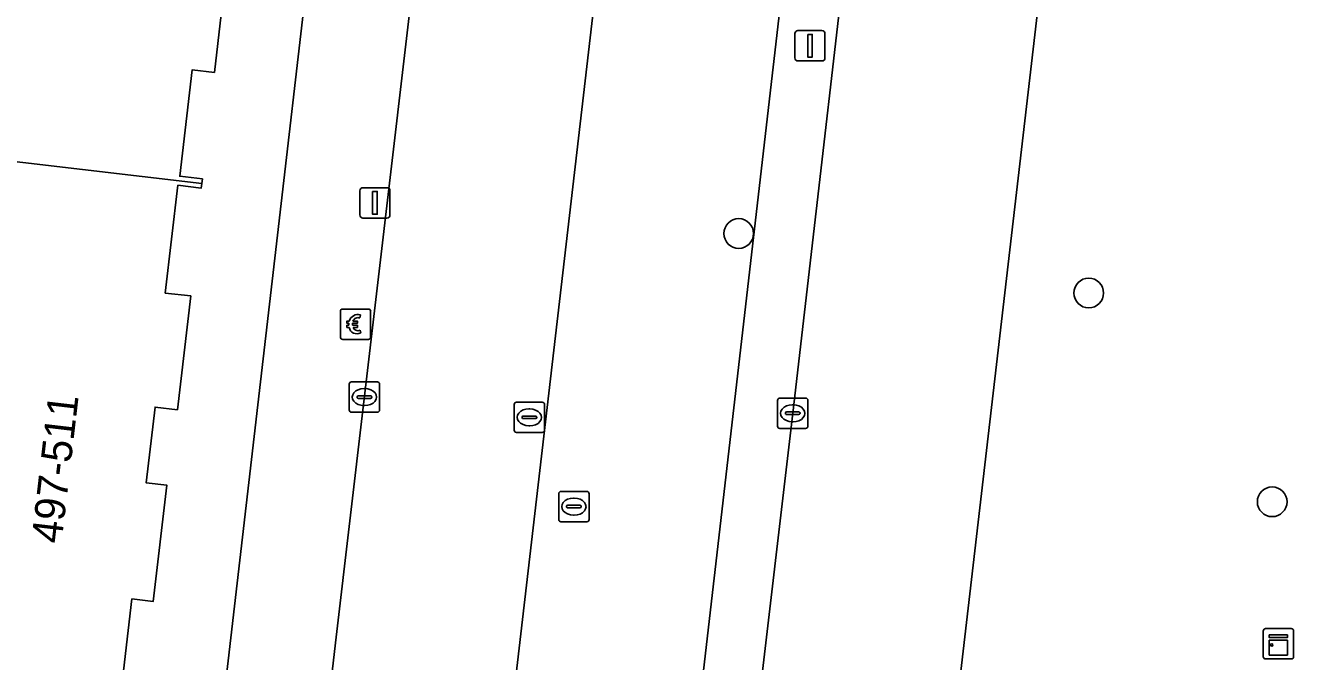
# Model space of a CAD drawing. Extents: x 160856 to 161310, y 384024 to 384878.
# Drawn here: x 161229.52 to 161271.35, y 384514 to 384534.96 of the extents above; entities that cross this region are included whole.
import ezdxf

# ---------------------------------------------------------------- set-up
doc = ezdxf.new("R2010")
doc.units = 0
for name, color, linetype in [('IMGEO_Berm_groen', 7, 'Continuous'), ('IMGEO_Betaalautomaat', 7, 'Continuous'), ('IMGEO_Boom', 7, 'Continuous'), ('IMGEO_Erf', 7, 'Continuous'), ('IMGEO_Kast', 7, 'Continuous'), ('IMGEO_Kolk', 7, 'Continuous'), ('IMGEO_Lichtmast', 7, 'Continuous'), ('IMGEO_Pand', 7, 'Continuous'), ('IMGEO_Pand_nummerreeks', 7, 'Continuous'), ('IMGEO_Parkeervlak_open', 7, 'Continuous'), ('IMGEO_Rijbaan_lokaal_gesloten', 7, 'Continuous'), ('IMGEO_Rijbaan_lokaal_open', 7, 'Continuous'), ('IMGEO_Rioolput', 7, 'Continuous'), ('IMGEO_Voetpad_open', 7, 'Continuous')]:
    doc.layers.add(name, color=color, linetype=linetype)

msp = doc.modelspace()

# ---------------------------------------------------------------- linework, layer by layer
at = {"layer": 'IMGEO_Berm_groen'}
for points in [[(161271.226, 384656.034), (161271.075, 384657.442), (161268.546, 384657.7), (161262.738, 384608.287), (161261.545, 384598.151), (161258.141, 384567.697), (161257.931, 384565.814), (161257.361, 384560.886), (161251.303, 384561.613), (161250.737, 384556.74), (161256.785, 384556.041), (161251.596, 384511.132), (161250.377, 384500), (161238.15, 384396.266), (161238.006, 384395.04), (161236.799, 384395.17)], [(161254.83, 384522.177), (161257.178, 384542.439), (161259.33, 384560.777), (161261.579, 384580.114), (161261.966, 384583.337)], [(161269.166, 384580.645), (161268.148, 384576.401), (161267.446, 384572.759), (161266.816, 384568.826), (161266.33, 384564.879), (161259.354, 384504.899), (161254.88, 384466.32), (161245.611, 384386.656)], [(161237.241, 384373.124), (161237.25, 384373.157), (161237.479, 384374.076), (161237.563, 384374.434), (161237.763, 384375.367), (161238.178, 384378.283), (161238.653, 384382.516), (161239.6, 384390.894), (161241.912, 384411.162), (161243.88, 384428.499), (161246.021, 384446.828), (161247.876, 384462.682), (161250.03, 384480.998), (161252.438, 384501.823), (161254.83, 384522.177)]]:
    msp.add_lwpolyline(points, dxfattribs=at)
at = {"layer": 'IMGEO_Betaalautomaat'}
for p, q in [((161239.911, 384524.688), (161239.911, 384525.529)), ((161239.911, 384525.529), (161239.911, 384524.688)), ((161239.986, 384525.612), (161240.827, 384525.612)), ((161240.827, 384525.612), (161239.986, 384525.612)), ((161240.91, 384525.538), (161240.91, 384524.697)), ((161240.91, 384524.697), (161240.91, 384525.538)), ((161240.194, 384525.076), (161240.194, 384525.144)), ((161240.315, 384525.144), (161240.315, 384525.076)), ((161240.573, 384525.417), (161240.556, 384525.317)), ((161240.56, 384524.911), (161240.582, 384524.824)), ((161240.836, 384524.613), (161239.995, 384524.613)), ((161239.995, 384524.613), (161240.836, 384524.613))]:
    msp.add_line(p, q, dxfattribs=at)
for points in [[(161240.194, 384525.144), (161240.125, 384525.144), (161240.125, 384525.213), (161240.204, 384525.213)], [(161240.199, 384525.007), (161240.125, 384525.007), (161240.125, 384525.076), (161240.194, 384525.076)], [(161240.326, 384525.213), (161240.473, 384525.213), (161240.473, 384525.144), (161240.315, 384525.144)], [(161240.315, 384525.076), (161240.473, 384525.076), (161240.473, 384525.007), (161240.329, 384525.007)]]:
    msp.add_lwpolyline(points, dxfattribs=at)
for centre, radius, start, end in [((161239.989, 384525.535), 0.0779, 92.4484, 184.2845), ((161239.989, 384525.535), 0.0779, 92.4484, 184.2845), ((161240.833, 384525.535), 0.0779, 2.4484, 94.2845), ((161240.833, 384525.535), 0.0779, 2.4484, 94.2845), ((161240.487, 384525.137), 0.293, 73.014, 165.0139), ((161240.493, 384525.15), 0.179, 69.3236, 159.5683), ((161239.989, 384524.691), 0.0779, 182.4484, 274.2845), ((161239.989, 384524.691), 0.0779, 182.4484, 274.2845), ((161240.46, 384525.062), 0.267, 191.8096, 297.0389), ((161240.493, 384525.077), 0.179, 202.7625, 291.8693), ((161240.833, 384524.691), 0.0779, 272.4484, 4.2845), ((161240.833, 384524.691), 0.0779, 272.4484, 4.2845)]:
    msp.add_arc(centre, radius, start, end, dxfattribs=at)
at = {"layer": 'IMGEO_Boom'}
for centre in [(161253.048, 384528.1), (161264.594, 384526.14), (161270.643, 384519.261)]:
    msp.add_circle(centre, 0.489, dxfattribs=at)
at = {"layer": 'IMGEO_Erf'}
for points in [[(161234.582, 384500), (161242.07, 384564.539)], [(161236.204, 384537.232), (161235.756, 384533.408), (161235.024, 384533.494), (161234.613, 384529.988), (161235.359, 384529.901), (161235.341, 384529.749), (161235.324, 384529.598), (161234.553, 384529.688), (161234.137, 384526.139), (161234.975, 384526.042), (161234.536, 384522.296), (161233.803, 384522.382), (161233.511, 384519.883), (161234.189, 384519.804), (161233.741, 384515.981), (161233.034, 384516.064), (161232.635, 384512.65)]]:
    msp.add_lwpolyline(points, dxfattribs=at)
at = {"layer": 'IMGEO_Kast'}
for p, q in [((161270.426, 384515.084), (161271.267, 384515.084)), ((161271.267, 384515.084), (161270.426, 384515.084)), ((161270.351, 384514.159), (161270.351, 384515)), ((161270.351, 384515), (161270.351, 384514.159)), ((161271.351, 384515.009), (161271.351, 384514.168)), ((161271.351, 384514.168), (161271.351, 384515.009)), ((161271.276, 384514.084), (161270.435, 384514.084)), ((161270.435, 384514.084), (161271.276, 384514.084))]:
    msp.add_line(p, q, dxfattribs=at)
for points in [[(161270.546, 384514.874), (161271.146, 384514.874), (161271.146, 384514.789), (161270.546, 384514.789), (161270.546, 384514.874)], [(161270.546, 384514.699), (161271.146, 384514.699), (161271.146, 384514.21), (161270.546, 384514.21), (161270.546, 384514.699)]]:
    msp.add_lwpolyline(points, dxfattribs=at)
msp.add_circle((161270.63, 384514.548), 0.0377, dxfattribs=at)
for centre, start, end in [((161270.429, 384515.006), 92.4484, 184.2845), ((161270.429, 384515.006), 92.4484, 184.2845), ((161271.273, 384515.006), 2.4484, 94.2845), ((161271.273, 384515.006), 2.4484, 94.2845), ((161270.429, 384514.162), 182.4484, 274.2845), ((161270.429, 384514.162), 182.4484, 274.2845), ((161271.273, 384514.162), 272.4484, 4.2845), ((161271.273, 384514.162), 272.4484, 4.2845)]:
    msp.add_arc(centre, 0.0779, start, end, dxfattribs=at)
at = {"layer": 'IMGEO_Kolk'}
for p, q in [((161240.204, 384522.286), (161240.204, 384523.138)), ((161240.279, 384523.212), (161241.131, 384523.212)), ((161240.692, 384522.992), (161240.717, 384522.992)), ((161241.205, 384523.138), (161241.205, 384522.286)), ((161240.463, 384522.706), (161240.463, 384522.718)), ((161240.901, 384522.669), (161240.503, 384522.669)), ((161240.506, 384522.755), (161240.904, 384522.755)), ((161240.947, 384522.718), (161240.947, 384522.706)), ((161254.329, 384521.751), (161254.329, 384522.603)), ((161254.404, 384522.677), (161255.256, 384522.677)), ((161255.33, 384522.603), (161255.33, 384521.751)), ((161241.131, 384522.212), (161240.279, 384522.212)), ((161240.715, 384522.432), (161240.69, 384522.432)), ((161245.644, 384521.618), (161245.644, 384522.47)), ((161245.719, 384522.544), (161246.571, 384522.544)), ((161246.132, 384522.324), (161246.157, 384522.324)), ((161246.645, 384522.47), (161246.645, 384521.618)), ((161254.588, 384522.171), (161254.588, 384522.183)), ((161254.631, 384522.22), (161255.029, 384522.22)), ((161254.817, 384522.457), (161254.842, 384522.457)), ((161255.072, 384522.183), (161255.072, 384522.171)), ((161245.903, 384522.038), (161245.903, 384522.05)), ((161246.341, 384522.001), (161245.943, 384522.001)), ((161245.946, 384522.087), (161246.344, 384522.087)), ((161246.155, 384521.764), (161246.13, 384521.764)), ((161246.387, 384522.05), (161246.387, 384522.038)), ((161255.026, 384522.134), (161254.628, 384522.134)), ((161254.84, 384521.897), (161254.815, 384521.897)), ((161246.571, 384521.544), (161245.719, 384521.544)), ((161255.256, 384521.677), (161254.404, 384521.677))]:
    msp.add_line(p, q, dxfattribs=at)
for points in [[(161240.204, 384522.286), (161240.204, 384523.138)], [(161240.279, 384523.212), (161241.131, 384523.212)], [(161241.205, 384523.138), (161241.205, 384522.286)], [(161254.329, 384521.751), (161254.329, 384522.603)], [(161254.404, 384522.677), (161255.256, 384522.677)], [(161255.33, 384522.603), (161255.33, 384521.751)], [(161241.131, 384522.212), (161240.279, 384522.212)], [(161245.644, 384521.618), (161245.644, 384522.47)], [(161245.719, 384522.544), (161246.571, 384522.544)], [(161246.645, 384522.47), (161246.645, 384521.618)], [(161246.571, 384521.544), (161245.719, 384521.544)], [(161255.256, 384521.677), (161254.404, 384521.677)]]:
    msp.add_lwpolyline(points, dxfattribs=at)
for centre, radius, start, end in [((161240.281, 384523.136), 0.0765, 91.552, 178.448), ((161240.281, 384523.136), 0.0765, 91.552, 178.448), ((161241.129, 384523.136), 0.0765, 1.552, 88.448), ((161241.129, 384523.136), 0.0765, 1.552, 88.448), ((161240.503, 384522.715), 0.0403, 85.8775, 175.7526), ((161240.5, 384522.705), 0.0366, 178.938, 274.7102), ((161240.904, 384522.712), 0.043, 264.8664, 352.4533), ((161240.908, 384522.717), 0.0386, 1.7309, 96.639), ((161254.406, 384522.601), 0.0765, 91.552, 178.448), ((161254.406, 384522.601), 0.0765, 91.552, 178.448), ((161255.254, 384522.601), 0.0765, 1.552, 88.448), ((161255.254, 384522.601), 0.0765, 1.552, 88.448), ((161240.281, 384522.288), 0.0765, 181.552, 268.448), ((161240.281, 384522.288), 0.0765, 181.552, 268.448), ((161241.129, 384522.288), 0.0765, 271.552, 358.448), ((161241.129, 384522.288), 0.0765, 271.552, 358.448), ((161245.721, 384522.468), 0.0765, 91.552, 178.448), ((161245.721, 384522.468), 0.0765, 91.552, 178.448), ((161246.569, 384522.468), 0.0765, 1.552, 88.448), ((161246.569, 384522.468), 0.0765, 1.552, 88.448), ((161254.628, 384522.18), 0.0403, 85.8775, 175.7526), ((161254.625, 384522.17), 0.0366, 178.938, 274.7102), ((161255.029, 384522.177), 0.043, 264.8664, 352.4533), ((161255.033, 384522.182), 0.0386, 1.7309, 96.639), ((161245.943, 384522.047), 0.0403, 85.8775, 175.7526), ((161245.94, 384522.037), 0.0366, 178.938, 274.7102), ((161246.344, 384522.044), 0.043, 264.8664, 352.4533), ((161246.348, 384522.049), 0.0386, 1.7309, 96.639), ((161254.406, 384521.753), 0.0765, 181.552, 268.448), ((161254.406, 384521.753), 0.0765, 181.552, 268.448), ((161255.254, 384521.753), 0.0765, 271.552, 358.448), ((161255.254, 384521.753), 0.0765, 271.552, 358.448), ((161245.721, 384521.62), 0.0765, 181.552, 268.448), ((161245.721, 384521.62), 0.0765, 181.552, 268.448), ((161246.569, 384521.62), 0.0765, 271.552, 358.448), ((161246.569, 384521.62), 0.0765, 271.552, 358.448)]:
    msp.add_arc(centre, radius, start, end, dxfattribs=at)
for centre, major_axis, ratio, start_param, end_param in [((161240.691, 384522.712), (-0.387, 0.002), 0.722429, 4.712389, 7.853982), ((161240.716, 384522.712), (-0.39, 0.002), 0.717154, 1.570796, 4.712389), ((161246.131, 384522.044), (-0.387, 0.002), 0.722429, 4.712389, 7.853982), ((161246.156, 384522.044), (-0.39, 0.002), 0.717154, 1.570796, 4.712389), ((161254.816, 384522.177), (-0.387, 0.002), 0.722429, 4.712389, 7.853982), ((161254.841, 384522.177), (-0.39, 0.002), 0.717154, 1.570796, 4.712389)]:
    msp.add_ellipse(centre, major_axis=major_axis, ratio=ratio, start_param=start_param, end_param=end_param, dxfattribs=at)
at = {"layer": 'IMGEO_Lichtmast'}
for p, q in [((161255.004, 384534.786), (161255.794, 384534.786)), ((161255.794, 384534.786), (161255.004, 384534.786)), ((161254.904, 384533.886), (161254.904, 384534.686)), ((161254.904, 384534.686), (161254.904, 384533.886)), ((161255.894, 384534.686), (161255.894, 384533.886)), ((161255.894, 384533.886), (161255.894, 384534.686)), ((161255.794, 384533.786), (161255.004, 384533.786)), ((161255.004, 384533.786), (161255.794, 384533.786)), ((161240.556, 384528.71), (161240.556, 384529.51)), ((161240.556, 384529.51), (161240.556, 384528.71)), ((161240.656, 384529.61), (161241.446, 384529.61)), ((161241.446, 384529.61), (161240.656, 384529.61)), ((161241.546, 384529.51), (161241.546, 384528.71)), ((161241.546, 384528.71), (161241.546, 384529.51)), ((161241.446, 384528.61), (161240.656, 384528.61)), ((161240.656, 384528.61), (161241.446, 384528.61))]:
    msp.add_line(p, q, dxfattribs=at)
for points in [[(161255.324, 384534.661), (161255.474, 384534.661), (161255.474, 384533.911), (161255.324, 384533.911), (161255.324, 384534.661)], [(161240.976, 384529.485), (161241.126, 384529.485), (161241.126, 384528.735), (161240.976, 384528.735), (161240.976, 384529.485)]]:
    msp.add_lwpolyline(points, dxfattribs=at)
for centre, start, end in [((161255.004, 384534.686), 90, 180), ((161255.004, 384534.686), 90, 180), ((161255.794, 384534.686), 0, 90), ((161255.794, 384534.686), 360, 90), ((161255.004, 384533.886), 180, 270), ((161255.004, 384533.886), 180, 270), ((161255.794, 384533.886), 270, 0), ((161255.794, 384533.886), 270, 0), ((161240.656, 384529.51), 90, 180), ((161240.656, 384529.51), 90, 180), ((161241.446, 384529.51), 0, 90), ((161241.446, 384529.51), 360, 90), ((161240.656, 384528.71), 180, 270), ((161240.656, 384528.71), 180, 270), ((161241.446, 384528.71), 270, 0), ((161241.446, 384528.71), 270, 0)]:
    msp.add_arc(centre, 0.1, start, end, dxfattribs=at)
at = {"layer": 'IMGEO_Pand'}
for points in [[(161223.524, 384531.132), (161235.341, 384529.749), (161235.359, 384529.901), (161234.613, 384529.988), (161235.024, 384533.494), (161235.756, 384533.408), (161236.204, 384537.232), (161235.524, 384537.311), (161235.817, 384539.821), (161236.552, 384539.735), (161236.996, 384543.537), (161236.224, 384543.627), (161236.617, 384546.979), (161237.389, 384546.889), (161237.443, 384547.35), (161232.751, 384547.898), (161230.709, 384548.137), (161225.533, 384548.667)], [(161232.635, 384512.65), (161233.034, 384516.064), (161233.741, 384515.981), (161234.189, 384519.804), (161233.511, 384519.883), (161233.803, 384522.382), (161234.536, 384522.296), (161234.975, 384526.042), (161234.137, 384526.139), (161234.553, 384529.688), (161235.324, 384529.598), (161235.341, 384529.749), (161223.524, 384531.132)]]:
    msp.add_lwpolyline(points, dxfattribs=at)
at = {"layer": 'IMGEO_Parkeervlak_open'}
for points in [[(161256.785, 384556.041), (161250.737, 384556.74), (161231.686, 384393.141)], [(161236.799, 384395.17), (161238.006, 384395.04), (161238.15, 384396.266), (161250.377, 384500), (161251.596, 384511.132), (161256.785, 384556.041)]]:
    msp.add_lwpolyline(points, dxfattribs=at)
at = {"layer": 'IMGEO_Rijbaan_lokaal_gesloten'}
for points in [[(161261.966, 384583.337), (161261.579, 384580.114), (161259.33, 384560.777), (161257.178, 384542.439), (161254.83, 384522.177), (161252.438, 384501.823), (161250.03, 384480.998), (161247.876, 384462.682), (161246.021, 384446.828), (161243.88, 384428.499), (161241.912, 384411.162), (161239.6, 384390.894), (161238.653, 384382.516), (161238.178, 384378.283), (161237.763, 384375.367), (161237.563, 384374.434), (161237.479, 384374.076), (161237.25, 384373.157), (161237.241, 384373.124), (161237.099, 384372.576), (161236.892, 384371.866), (161236.493, 384370.578)], [(161245.611, 384386.656), (161254.88, 384466.32), (161259.354, 384504.899), (161266.33, 384564.879), (161266.816, 384568.826), (161267.446, 384572.759), (161268.148, 384576.401), (161269.166, 384580.645)]]:
    msp.add_lwpolyline(points, dxfattribs=at)
at = {"layer": 'IMGEO_Rijbaan_lokaal_open'}
for points in [[(161253.842, 384635.509), (161253.738, 384634.519), (161250.766, 384609.622), (161249.855, 384601.831), (161243.381, 384545.472), (161239.778, 384514.805), (161238.057, 384500), (161237.777, 384496.96), (161237.656, 384495.995), (161237.846, 384495.256), (161238.878, 384493.86)], [(161236.821, 384488.628), (161236.635, 384487.009), (161235.532, 384478.284), (161231.826, 384447.259), (161225.155, 384389.562), (161224.63, 384384.341), (161229.978, 384383.71), (161230.652, 384383.631), (161231.223, 384389.168), (161231.686, 384393.141), (161250.737, 384556.74)]]:
    msp.add_lwpolyline(points, dxfattribs=at)
at = {"layer": 'IMGEO_Rioolput'}
for p, q in [((161247.112, 384518.676), (161247.112, 384519.528)), ((161247.187, 384519.602), (161248.039, 384519.602)), ((161247.6, 384519.382), (161247.625, 384519.382)), ((161248.113, 384519.528), (161248.113, 384518.676)), ((161247.371, 384519.096), (161247.371, 384519.108)), ((161247.809, 384519.059), (161247.411, 384519.059)), ((161247.414, 384519.145), (161247.812, 384519.145)), ((161247.623, 384518.822), (161247.598, 384518.822)), ((161247.855, 384519.108), (161247.855, 384519.096)), ((161248.039, 384518.602), (161247.187, 384518.602))]:
    msp.add_line(p, q, dxfattribs=at)
for points in [[(161247.112, 384518.676), (161247.112, 384519.528)], [(161247.187, 384519.602), (161248.039, 384519.602)], [(161248.113, 384519.528), (161248.113, 384518.676)], [(161248.039, 384518.602), (161247.187, 384518.602)]]:
    msp.add_lwpolyline(points, dxfattribs=at)
for centre, radius, start, end in [((161247.189, 384519.526), 0.0765, 91.552, 178.448), ((161247.189, 384519.526), 0.0765, 91.552, 178.448), ((161248.037, 384519.526), 0.0765, 1.552, 88.448), ((161248.037, 384519.526), 0.0765, 1.552, 88.448), ((161247.411, 384519.105), 0.0403, 85.8775, 175.7526), ((161247.408, 384519.095), 0.0366, 178.938, 274.7102), ((161247.812, 384519.102), 0.043, 264.8664, 352.4533), ((161247.816, 384519.107), 0.0386, 1.7309, 96.639), ((161247.189, 384518.678), 0.0765, 181.552, 268.448), ((161247.189, 384518.678), 0.0765, 181.552, 268.448), ((161248.037, 384518.678), 0.0765, 271.552, 358.448), ((161248.037, 384518.678), 0.0765, 271.552, 358.448)]:
    msp.add_arc(centre, radius, start, end, dxfattribs=at)
for centre, major_axis, ratio, start_param, end_param in [((161247.599, 384519.102), (-0.387, 0.002), 0.722429, 4.712389, 7.853982), ((161247.624, 384519.102), (-0.39, 0.002), 0.717154, 1.570796, 4.712389)]:
    msp.add_ellipse(centre, major_axis=major_axis, ratio=ratio, start_param=start_param, end_param=end_param, dxfattribs=at)
at = {"layer": 'IMGEO_Voetpad_open'}
msp.add_lwpolyline([(161242.07, 384564.539), (161234.582, 384500), (161233.969, 384494.717), (161237.656, 384495.995), (161237.777, 384496.96), (161238.057, 384500), (161239.778, 384514.805), (161243.381, 384545.472), (161249.855, 384601.831)], dxfattribs=at)

# ---------------------------------------------------------------- texts
at = {"layer": 'IMGEO_Pand_nummerreeks'}
msp.add_text('497-511', height=1, rotation=83.3424, dxfattribs=at).set_placement((161230.711, 384517.86))

doc.saveas('drawing.dxf')
